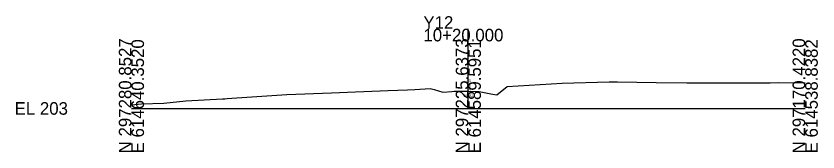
# Model space of a CAD drawing. Extents: x 517327 to 517505, y 114839 to 117367.
# Drawn here: x 517326.7 to 517505.2, y 115338.7 to 115368.9 of the extents above; entities that cross this region are included whole.
import ezdxf

# ---------------------------------------------------------------- set-up
doc = ezdxf.new("R2010")
doc.units = 0
for name, color, linetype in [('Exist XS Ground Line', 7, 'Continuous'), ('Old_Level_59', 7, 'Continuous'), ('Old_Level_63', 7, 'Continuous')]:
    doc.layers.add(name, color=color, linetype=linetype)

msp = doc.modelspace()

# ---------------------------------------------------------------- linework, layer by layer
at = {"layer": 'Exist XS Ground Line'}
for p, q in [((517415.44, 115352.58), (517418.85, 115352.79)), ((517418.85, 115352.79), (517419.78, 115352.54)), ((517433.71, 115351.37), (517436, 115353.27)), ((517436, 115353.27), (517448.23, 115353.96)), ((517448.23, 115353.96), (517458.69, 115354.26)), ((517458.69, 115354.26), (517460.54, 115354.27)), ((517460.54, 115354.27), (517469.17, 115354.1)), ((517469.17, 115354.1), (517476.03, 115354.08)), ((517476.03, 115354.08), (517482.26, 115354.04)), ((517482.26, 115354.04), (517488.83, 115354.06)), ((517488.83, 115354.06), (517494.55, 115354.04)), ((517494.55, 115354.04), (517496.33, 115354.14)), ((517496.33, 115354.14), (517502.36, 115354.08)), ((517374.71, 115350.64), (517386.96, 115351.46)), ((517386.96, 115351.46), (517396.93, 115351.86)), ((517396.93, 115351.86), (517400.5, 115352.01)), ((517400.5, 115352.01), (517409.53, 115352.33)), ((517409.53, 115352.33), (517413.81, 115352.52)), ((517413.81, 115352.52), (517415.44, 115352.58)), ((517419.78, 115352.54), (517421.72, 115351.98)), ((517421.72, 115351.98), (517423.7, 115352.14)), ((517423.7, 115352.14), (517424.2, 115352.18)), ((517424.2, 115352.18), (517424.64, 115352.17)), ((517424.64, 115352.17), (517427.18, 115352.19)), ((517427.18, 115352.19), (517429.78, 115352.11)), ((517429.78, 115352.11), (517430.14, 115352.09)), ((517430.14, 115352.09), (517432.35, 115351.64)), ((517432.35, 115351.64), (517433.71, 115351.37)), ((517352.36, 115349.19), (517354.61, 115349.39)), ((517354.61, 115349.39), (517359.55, 115349.52)), ((517359.55, 115349.52), (517364.49, 115350.02)), ((517364.49, 115350.02), (517372.65, 115350.49)), ((517372.65, 115350.49), (517373.16, 115350.53)), ((517373.16, 115350.53), (517373.66, 115350.56)), ((517373.66, 115350.56), (517374.71, 115350.64))]:
    msp.add_line(p, q, dxfattribs=at)
at = {"layer": 'Old_Level_63'}
for p, q in [((517427.36, 115348.36), (517427.36, 115366.09)), ((517352.36, 115348.36), (517427.36, 115348.36)), ((517427.36, 115348.36), (517502.36, 115348.36))]:
    msp.add_line(p, q, dxfattribs=at)

# ---------------------------------------------------------------- texts
at = {"layer": 'Old_Level_59'}
msp.add_text(' 206.818', height=0.5, rotation=90, dxfattribs=at).set_placement((517427.86, 115352.18))
msp.add_text(' 206.818', height=0.5, rotation=90, dxfattribs=at).set_placement((517427.86, 115352.18))
msp.add_text(' 206.818', height=0.5, rotation=90, dxfattribs=at).set_placement((517427.86, 115352.18))
msp.add_text('206.82', height=0.5, dxfattribs=at).set_placement((517426.31, 115350.93))
at = {"layer": 'Old_Level_63'}
for s, p in [('Y12', (517417.36, 115366.09)), ('10+20.000', (517417.37, 115363.29)), ('EL 203', (517326.36, 115346.96))]:
    msp.add_text(s, height=2.8, dxfattribs=at).set_placement(p)
for s, p in [('N 297280.8527', (517352.36, 115338.37)), ('E 614640.3520', (517355.16, 115338.36)), ('N 297225.6373', (517427.36, 115338.36)), ('E 614589.5951', (517430.16, 115338.37)), ('N 297170.4220', (517502.36, 115338.36)), ('E 614538.8382', (517505.16, 115338.36))]:
    msp.add_text(s, height=2.8, rotation=90, dxfattribs=at).set_placement(p)

doc.saveas('drawing.dxf')
